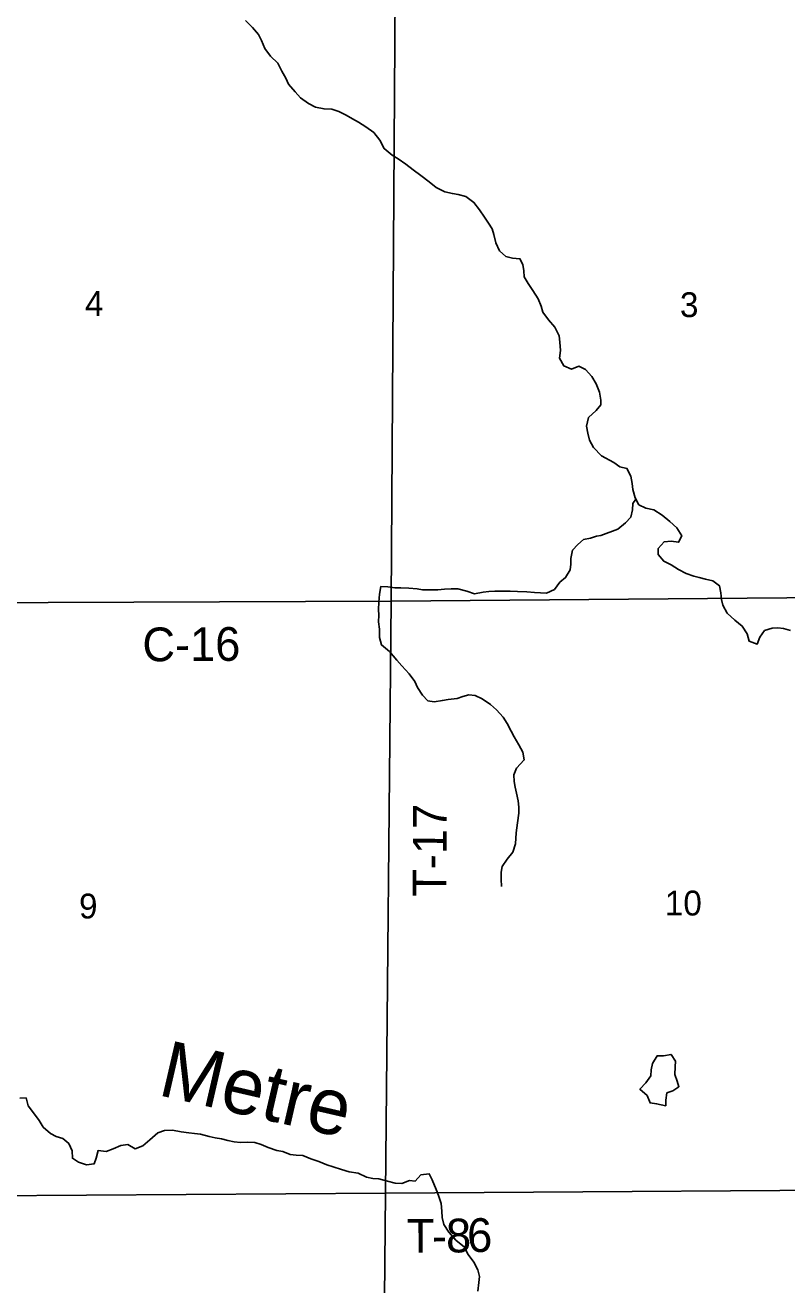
# Model space of a CAD drawing. Extents: x 1772825 to 1773716, y 1138558 to 1139032.
# Drawn here: x 1772829.187 to 1772829.828, y 1138560.049 to 1138561.109 of the extents above; entities that cross this region are included whole.
import ezdxf

# ---------------------------------------------------------------- set-up
doc = ezdxf.new("R2010")
doc.units = 0
for name, color, linetype in [('GM_X_County_Road_Text', 7, 'Continuous'), ('GM_X_Minor_Lake', 7, 'Continuous'), ('GM_X_Minor_River', 7, 'Continuous'), ('GM_X_Minor_River_Text', 7, 'Continuous'), ('GM_X_Section', 7, 'Continuous'), ('GM_X_Section_Text', 7, 'Continuous'), ('GM_X_Township_Road_Text', 7, 'Continuous')]:
    doc.layers.add(name, color=color, linetype=linetype)

msp = doc.modelspace()

# ---------------------------------------------------------------- linework, layer by layer
at = {"layer": 'GM_X_Minor_Lake'}
for points in [[(1772829.7203, 1138560.2418), (1772829.7187, 1138560.2418), (1772829.7147, 1138560.2355), (1772829.7137, 1138560.23), (1772829.7133, 1138560.2249), (1772829.7091, 1138560.219), (1772829.7043, 1138560.2137), (1772829.7102, 1138560.2084), (1772829.7128, 1138560.2023), (1772829.7183, 1138560.2015), (1772829.7259, 1138560.1998)], [(1772829.7259, 1138560.1998), (1772829.7259, 1138560.2045), (1772829.7269, 1138560.2106), (1772829.732, 1138560.2123), (1772829.737, 1138560.2159), (1772829.7355, 1138560.2206), (1772829.7336, 1138560.2261), (1772829.734, 1138560.2326), (1772829.7342, 1138560.2373), (1772829.7304, 1138560.243), (1772829.7242, 1138560.2419), (1772829.7203, 1138560.2418)]]:
    msp.add_lwpolyline(points, dxfattribs=at)
at = {"layer": 'GM_X_Minor_River'}
for points in [[(1772829.3725, 1138561.1133), (1772829.3784, 1138561.1076), (1772829.3835, 1138561.1017), (1772829.3861, 1138561.0964), (1772829.3887, 1138561.0899), (1772829.3934, 1138561.0834), (1772829.3996, 1138561.0775), (1772829.4032, 1138561.0708), (1772829.4065, 1138561.0647), (1772829.4088, 1138561.0598), (1772829.4142, 1138561.0533), (1772829.4187, 1138561.0483), (1772829.4254, 1138561.0435), (1772829.4314, 1138561.0404), (1772829.4386, 1138561.039), (1772829.445, 1138561.0388), (1772829.4511, 1138561.0369), (1772829.4573, 1138561.0338), (1772829.4626, 1138561.0305), (1772829.4675, 1138561.0278), (1772829.4736, 1138561.024), (1772829.4804, 1138561.019), (1772829.4855, 1138561.0127), (1772829.489, 1138561.0055), (1772829.4958, 1138561.0001), (1772829.5009, 1138560.997), (1772829.5073, 1138560.9924), (1772829.5135, 1138560.9878), (1772829.52, 1138560.983), (1772829.5269, 1138560.9775), (1772829.5328, 1138560.9729), (1772829.5402, 1138560.9692), (1772829.5466, 1138560.9677), (1772829.5515, 1138560.967), (1772829.5578, 1138560.9653), (1772829.5646, 1138560.9603), (1772829.5693, 1138560.954), (1772829.5734, 1138560.9477), (1772829.577, 1138560.9428), (1772829.58, 1138560.938)], [(1772829.58, 1138560.938), (1772829.5814, 1138560.9332), (1772829.5831, 1138560.9262), (1772829.5861, 1138560.9196), (1772829.5916, 1138560.9146), (1772829.597, 1138560.9134), (1772829.6033, 1138560.9128), (1772829.6057, 1138560.908), (1772829.6065, 1138560.9027), (1772829.6068, 1138560.8976), (1772829.6102, 1138560.8921), (1772829.6143, 1138560.886), (1772829.6186, 1138560.8791), (1772829.6212, 1138560.873), (1772829.6225, 1138560.8679), (1772829.6274, 1138560.8614), (1772829.6327, 1138560.8551), (1772829.6362, 1138560.8478), (1772829.6369, 1138560.8427), (1772829.6373, 1138560.8357), (1772829.6366, 1138560.8291), (1772829.6402, 1138560.8228), (1772829.6468, 1138560.8199), (1772829.6529, 1138560.8225), (1772829.6586, 1138560.8196), (1772829.6637, 1138560.8137), (1772829.6674, 1138560.8076), (1772829.6702, 1138560.8006), (1772829.6715, 1138560.7938), (1772829.6715, 1138560.7898), (1772829.6674, 1138560.785), (1772829.6611, 1138560.7792), (1772829.6592, 1138560.772), (1772829.6603, 1138560.7659), (1772829.6619, 1138560.7602), (1772829.6651, 1138560.7539), (1772829.672, 1138560.7469)], [(1772829.672, 1138560.7469), (1772829.6823, 1138560.7412), (1772829.6873, 1138560.7376), (1772829.6933, 1138560.7364), (1772829.6967, 1138560.7298), (1772829.6976, 1138560.7235), (1772829.6982, 1138560.7186), (1772829.7002, 1138560.7117), (1772829.7034, 1138560.7057), (1772829.7093, 1138560.7028), (1772829.7158, 1138560.7014), (1772829.7229, 1138560.697), (1772829.7294, 1138560.6917), (1772829.7352, 1138560.6862), (1772829.7394, 1138560.6797), (1772829.7367, 1138560.6742), (1772829.7306, 1138560.675), (1772829.7246, 1138560.6746), (1772829.7196, 1138560.669), (1772829.7196, 1138560.6639), (1772829.7243, 1138560.6583), (1772829.7304, 1138560.6553), (1772829.7366, 1138560.6513), (1772829.7432, 1138560.648), (1772829.7495, 1138560.6455), (1772829.7542, 1138560.6444), (1772829.7593, 1138560.6432), (1772829.7656, 1138560.6417), (1772829.7711, 1138560.6375), (1772829.7724, 1138560.6316), (1772829.7729, 1138560.6261), (1772829.774, 1138560.6213), (1772829.7776, 1138560.6145), (1772829.784, 1138560.6086), (1772829.7903, 1138560.6036), (1772829.7944, 1138560.5971), (1772829.7961, 1138560.5909), (1772829.8029, 1138560.5884), (1772829.8051, 1138560.5943), (1772829.8091, 1138560.5999), (1772829.8155, 1138560.6018), (1772829.8203, 1138560.602), (1772829.825, 1138560.6016), (1772829.8309, 1138560.5998)], [(1772829.7009, 1138560.7105), (1772829.6983, 1138560.7068), (1772829.6979, 1138560.7015), (1772829.6967, 1138560.6954), (1772829.692, 1138560.6905), (1772829.6857, 1138560.6852), (1772829.6715, 1138560.6799)], [(1772829.6715, 1138560.6799), (1772829.6678, 1138560.6794), (1772829.6628, 1138560.6775), (1772829.6568, 1138560.6764), (1772829.652, 1138560.6723), (1772829.6476, 1138560.6674), (1772829.6462, 1138560.6606), (1772829.6462, 1138560.6558), (1772829.6456, 1138560.6511), (1772829.6417, 1138560.6445), (1772829.6369, 1138560.6405), (1772829.6323, 1138560.6345), (1772829.6257, 1138560.6313), (1772829.6206, 1138560.6315), (1772829.6156, 1138560.6318), (1772829.609, 1138560.6324), (1772829.6012, 1138560.6326), (1772829.595, 1138560.6329), (1772829.5822, 1138560.633), (1772829.5773, 1138560.6328), (1772829.5724, 1138560.6323), (1772829.5652, 1138560.6308), (1772829.5587, 1138560.633), (1772829.551, 1138560.6351), (1772829.5455, 1138560.635), (1772829.5398, 1138560.6346), (1772829.5343, 1138560.6341), (1772829.5215, 1138560.6342), (1772829.5168, 1138560.635), (1772829.51, 1138560.6354), (1772829.5031, 1138560.6357), (1772829.4982, 1138560.6359), (1772829.4922, 1138560.6367), (1772829.4863, 1138560.6369), (1772829.4853, 1138560.6305), (1772829.4847, 1138560.6238), (1772829.4844, 1138560.6176), (1772829.4846, 1138560.6128), (1772829.4845, 1138560.6073), (1772829.4851, 1138560.6009), (1772829.4852, 1138560.5941), (1772829.487, 1138560.5878), (1772829.4936, 1138560.5821), (1772829.4998, 1138560.575), (1772829.504, 1138560.5702), (1772829.5102, 1138560.5635), (1772829.5149, 1138560.557), (1772829.5171, 1138560.5519), (1772829.5213, 1138560.5454), (1772829.526, 1138560.5407), (1772829.5311, 1138560.5399), (1772829.5381, 1138560.5411), (1772829.5429, 1138560.5417), (1772829.5506, 1138560.5427), (1772829.5554, 1138560.5444), (1772829.5603, 1138560.5457), (1772829.5657, 1138560.5453), (1772829.5715, 1138560.5424), (1772829.5785, 1138560.5376), (1772829.5836, 1138560.5332), (1772829.5892, 1138560.5269), (1772829.5926, 1138560.5216), (1772829.596, 1138560.5151), (1772829.5986, 1138560.5103), (1772829.6025, 1138560.5037), (1772829.6057, 1138560.4974), (1772829.607, 1138560.4909), (1772829.6003, 1138560.4841), (1772829.5982, 1138560.4783), (1772829.5985, 1138560.4728), (1772829.5992, 1138560.468), (1772829.6003, 1138560.4631), (1772829.6018, 1138560.4564), (1772829.6023, 1138560.4513), (1772829.6025, 1138560.4462), (1772829.6013, 1138560.4379), (1772829.6001, 1138560.4297), (1772829.5996, 1138560.4202), (1772829.5973, 1138560.4134), (1772829.5927, 1138560.4074), (1772829.5885, 1138560.4013), (1772829.5875, 1138560.3964), (1772829.5876, 1138560.3907), (1772829.5878, 1138560.3843)], [(1772829.1827, 1138560.2062), (1772829.188, 1138560.2065), (1772829.1897, 1138560.1999), (1772829.1942, 1138560.194), (1772829.1991, 1138560.1875), (1772829.2024, 1138560.1819), (1772829.2085, 1138560.1764), (1772829.2134, 1138560.1739), (1772829.2189, 1138560.1723), (1772829.2238, 1138560.1681), (1772829.2268, 1138560.1618), (1772829.2269, 1138560.1556), (1772829.232, 1138560.1523), (1772829.2388, 1138560.15), (1772829.2451, 1138560.1509), (1772829.2468, 1138560.1558), (1772829.2486, 1138560.1623), (1772829.2552, 1138560.1614), (1772829.2611, 1138560.1635), (1772829.2678, 1138560.1665), (1772829.2735, 1138560.1672), (1772829.2797, 1138560.1637), (1772829.2862, 1138560.1661), (1772829.2921, 1138560.1712), (1772829.2988, 1138560.1771), (1772829.3045, 1138560.1791), (1772829.3111, 1138560.1794), (1772829.3185, 1138560.178), (1772829.3248, 1138560.177), (1772829.3297, 1138560.1766), (1772829.3346, 1138560.1758), (1772829.342, 1138560.1739), (1772829.347, 1138560.1729), (1772829.3523, 1138560.1721), (1772829.3576, 1138560.1707), (1772829.3629, 1138560.1696), (1772829.3682, 1138560.1688), (1772829.3739, 1138560.1691), (1772829.3805, 1138560.1688), (1772829.3858, 1138560.1671), (1772829.3917, 1138560.1648), (1772829.3989, 1138560.1623), (1772829.404, 1138560.1613), (1772829.4102, 1138560.1588), (1772829.4151, 1138560.1582), (1772829.4206, 1138560.1579), (1772829.4275, 1138560.1552), (1772829.4341, 1138560.1529), (1772829.4409, 1138560.1502), (1772829.4462, 1138560.1484), (1772829.4532, 1138560.1461), (1772829.4598, 1138560.1442), (1772829.4672, 1138560.1432), (1772829.4742, 1138560.1397), (1772829.4797, 1138560.1387), (1772829.4846, 1138560.1383), (1772829.4918, 1138560.1365), (1772829.4985, 1138560.1348), (1772829.5041, 1138560.1345), (1772829.5104, 1138560.1368), (1772829.5152, 1138560.1363), (1772829.5201, 1138560.1418), (1772829.527, 1138560.1425), (1772829.5294, 1138560.1374), (1772829.5314, 1138560.1326), (1772829.5337, 1138560.1273), (1772829.5355, 1138560.1225), (1772829.537, 1138560.1176), (1772829.5376, 1138560.1111), (1772829.5379, 1138560.1058), (1772829.5392, 1138560.0999), (1772829.5435, 1138560.0933), (1772829.5497, 1138560.0864), (1772829.5563, 1138560.0812), (1772829.5599, 1138560.0747), (1772829.5646, 1138560.0683), (1772829.5679, 1138560.0616), (1772829.5692, 1138560.0561), (1772829.5688, 1138560.0512), (1772829.568, 1138560.0438)]]:
    msp.add_lwpolyline(points, dxfattribs=at)
at = {"layer": 'GM_X_Section'}
for points in [[(1772828.9965, 1138561.1389), (1772829.002, 1138561.1389), (1772829.4984, 1138561.1377), (1772829.4949, 1138560.6247), (1772828.9898, 1138560.6225)], [(1772829.4984, 1138561.1377), (1772829.9975, 1138561.1313), (1772829.9939, 1138560.6288), (1772829.4949, 1138560.6247)], [(1772829.4949, 1138560.6247), (1772829.9939, 1138560.6288), (1772829.988, 1138560.1296), (1772829.4902, 1138560.1262)], [(1772829.4949, 1138560.6247), (1772829.4902, 1138560.1262), (1772828.9871, 1138560.1228), (1772828.9898, 1138560.6225)], [(1772829.988, 1138560.1296), (1772829.979, 1138559.628), (1772829.4854, 1138559.6261), (1772829.4902, 1138560.1262)], [(1772829.4902, 1138560.1262), (1772829.4854, 1138559.6261), (1772828.9792, 1138559.622), (1772828.9871, 1138560.1228)]]:
    msp.add_lwpolyline(points, close=True, dxfattribs=at)

# ---------------------------------------------------------------- texts
at = {"layer": 'GM_X_County_Road_Text'}
msp.add_text('C-16', height=0.02841, rotation=0.3485, dxfattribs=at).set_placement((1772829.2859, 1138560.5739))
at = {"layer": 'GM_X_Minor_River_Text'}
msp.add_text('Metre', height=0.04736, rotation=347.017, dxfattribs=at).set_placement((1772829.2977, 1138560.2091))
at = {"layer": 'GM_X_Section_Text'}
for s, height, p in [('4', 0.0209, (1772829.2375, 1138560.8647)), ('3', 0.0209, (1772829.7379, 1138560.8637)), ('9', 0.0209, (1772829.2325, 1138560.3575)), ('10', 0.02093, (1772829.7252, 1138560.36))]:
    msp.add_text(s, height=height, rotation=0, dxfattribs=at).set_placement(p)
at = {"layer": 'GM_X_Township_Road_Text'}
for s, height, rotation, p in [('T-17', 0.02841, 89.6542, (1772829.5414, 1138560.3757)), ('T', 0.0284, 0.4029, (1772829.5083, 1138560.0761)), ('8', 0.0284, 0.5644, (1772829.5413, 1138560.0763)), ('6', 0.0284, 1.3153, (1772829.5592, 1138560.0765)), ('-', 0.0284, 0.4391, (1772829.5295, 1138560.0762))]:
    msp.add_text(s, height=height, rotation=rotation, dxfattribs=at).set_placement(p)

doc.saveas('drawing.dxf')
